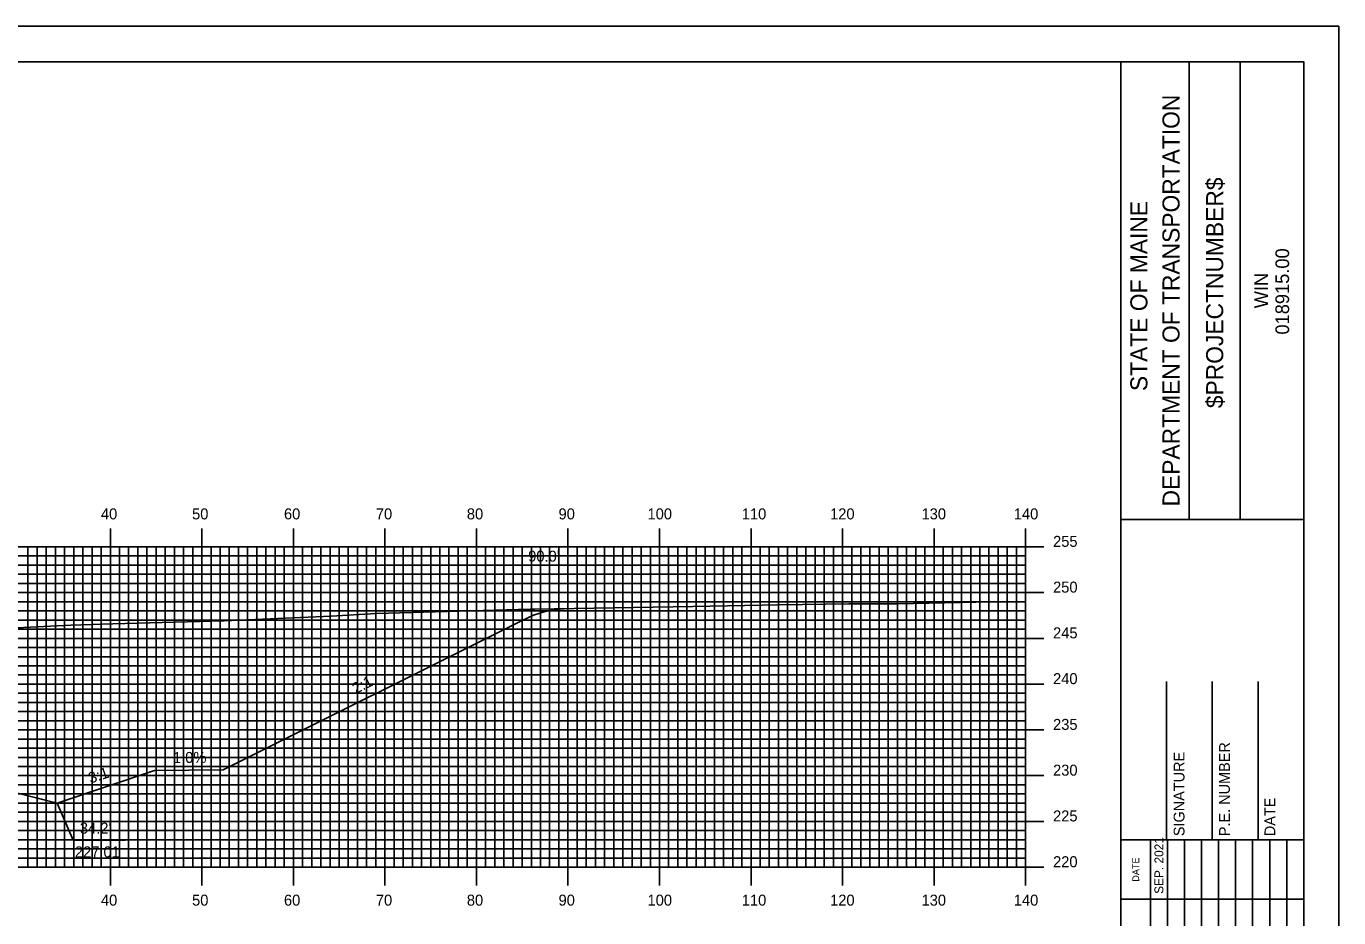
# Model space of a CAD drawing. Extents: x 1817670 to 1818013, y 442591 to 442811.
# Drawn here: x 1817866.4 to 1818009.8, y 442713.1 to 442810.5 of the extents above; entities that cross this region are included whole.
import ezdxf

# ---------------------------------------------------------------- set-up
doc = ezdxf.new("R2010")
doc.units = 0
for name, color, linetype in [('ANNOTATION', 7, 'Continuous'), ('BORDER', 7, 'Continuous'), ('D_Roadway_Centerline', 7, 'Continuous'), ('D_Roadway_SlopeLines', 7, 'Continuous'), ('D_Text_Standard', 7, 'Continuous'), ('H_V ANNOTATION', 7, 'Continuous'), ('MAJOR', 7, 'Continuous'), ('MINOR', 7, 'Continuous'), ('PLOT BOUNDARY', 7, 'Continuous'), ('S_Roadway_Centerline', 7, 'Continuous')]:
    doc.layers.add(name, color=color, linetype=linetype)

msp = doc.modelspace()

# ---------------------------------------------------------------- linework, layer by layer
at = {"layer": 'ANNOTATION'}
msp.add_lwpolyline([(1817877.24, 442721.62), (1817871.55, 442721.62), (1817869.79, 442725.67)], dxfattribs=at)
at = {"layer": 'BORDER'}
for p, q in [((1817986.01, 442596.67), (1817986.01, 442806.67)), ((1817993.47, 442756.66), (1817993.47, 442806.66)), ((1817999.06, 442756.66), (1817999.06, 442806.66)), ((1817986.01, 442756.65), (1818006.01, 442756.65)), ((1817991.01, 442721.67), (1817991.01, 442738.97)), ((1817996.01, 442721.67), (1817996.01, 442738.97)), ((1818001.01, 442721.67), (1818001.01, 442738.97)), ((1817986.01, 442721.67), (1818006.01, 442721.67))]:
    msp.add_line(p, q, dxfattribs=at)
msp.add_lwpolyline([(1817686.01, 442596.67), (1818006.01, 442596.67), (1818006.01, 442806.67), (1817686.01, 442806.67)], close=True, dxfattribs=at)
for points in [[(1817989.24, 442715.17), (1817989.24, 442721.67)], [(1817991.11, 442686.68), (1817991.11, 442721.67)], [(1817992.97, 442721.67), (1817992.97, 442686.68)], [(1817994.83, 442686.68), (1817994.83, 442721.67)], [(1817996.7, 442686.68), (1817996.7, 442721.67)], [(1817998.56, 442686.68), (1817998.56, 442721.67)], [(1818000.42, 442686.68), (1818000.42, 442721.67)], [(1818002.29, 442686.68), (1818002.29, 442721.67)], [(1818004.15, 442686.68), (1818004.15, 442721.67)], [(1817989.24, 442686.68), (1817989.24, 442720.26)], [(1817986.01, 442715.17), (1818006.01, 442715.17)]]:
    msp.add_lwpolyline(points, dxfattribs=at)
at = {"layer": 'D_Roadway_Centerline'}
msp.add_lwpolyline([(1817745.61, 442736.37), (1817746.86, 442736.45), (1817748.11, 442736.32), (1817749.36, 442736), (1817750.61, 442735.48), (1817762.56, 442729.5), (1817790.81, 442729.22), (1817801.44, 442725.67), (1817805.44, 442726.67), (1817815.61, 442729.22), (1817823.61, 442729.54), (1817835.61, 442729.78), (1817847.61, 442729.54), (1817855.61, 442729.22), (1817865.79, 442726.67), (1817869.79, 442725.67), (1817880.42, 442729.22), (1817887.92, 442729.29), (1817920.61, 442745.64), (1817921.86, 442746.19), (1817923.11, 442746.59), (1817924.36, 442746.83), (1817925.61, 442746.93)], dxfattribs=at)
at = {"layer": 'D_Roadway_SlopeLines'}
for points in [[(1817880.42, 442729.22), (1817887.92, 442729.29), (1817920.61, 442745.64), (1817921.86, 442746.19), (1817923.11, 442746.59), (1817924.36, 442746.83), (1817925.61, 442746.93)], [(1817855.61, 442729.22), (1817869.79, 442725.67)], [(1817869.79, 442725.67), (1817880.42, 442729.22)]]:
    msp.add_lwpolyline(points, dxfattribs=at)
at = {"layer": 'MAJOR'}
for p, q in [((1817875.61, 442755.67), (1817875.61, 442753.67)), ((1817885.61, 442755.67), (1817885.61, 442753.67)), ((1817895.61, 442755.67), (1817895.61, 442753.67)), ((1817905.61, 442755.67), (1817905.61, 442753.67)), ((1817915.61, 442755.67), (1817915.61, 442753.67)), ((1817925.61, 442755.67), (1817925.61, 442753.67)), ((1817935.61, 442755.67), (1817935.61, 442753.67)), ((1817945.61, 442755.67), (1817945.61, 442753.67)), ((1817955.61, 442755.67), (1817955.61, 442753.67)), ((1817965.61, 442755.67), (1817965.61, 442753.67)), ((1817975.61, 442755.67), (1817975.61, 442753.67)), ((1817695.61, 442753.67), (1817975.61, 442753.67)), ((1817695.61, 442753.67), (1817975.61, 442753.67)), ((1817875.61, 442718.67), (1817875.61, 442753.67)), ((1817885.61, 442718.67), (1817885.61, 442753.67)), ((1817895.61, 442718.67), (1817895.61, 442753.67)), ((1817905.61, 442718.67), (1817905.61, 442753.67)), ((1817915.61, 442718.67), (1817915.61, 442753.67)), ((1817925.61, 442718.67), (1817925.61, 442753.67)), ((1817935.61, 442718.67), (1817935.61, 442753.67)), ((1817945.61, 442718.67), (1817945.61, 442753.67)), ((1817955.61, 442718.67), (1817955.61, 442753.67)), ((1817965.61, 442718.67), (1817965.61, 442753.67)), ((1817977.62, 442753.67), (1817973.61, 442753.67)), ((1817975.61, 442718.67), (1817975.61, 442753.67)), ((1817975.61, 442718.67), (1817975.61, 442753.67)), ((1817695.61, 442748.67), (1817975.61, 442748.67)), ((1817977.62, 442748.67), (1817973.61, 442748.67)), ((1817695.61, 442743.67), (1817975.61, 442743.67)), ((1817977.62, 442743.67), (1817973.61, 442743.67)), ((1817695.61, 442738.67), (1817975.61, 442738.67)), ((1817977.62, 442738.67), (1817973.61, 442738.67)), ((1817695.61, 442733.67), (1817975.61, 442733.67)), ((1817977.62, 442733.67), (1817973.61, 442733.67)), ((1817695.61, 442728.67), (1817975.61, 442728.67)), ((1817977.62, 442728.67), (1817973.61, 442728.67)), ((1817695.61, 442723.67), (1817975.61, 442723.67)), ((1817977.62, 442723.67), (1817973.61, 442723.67)), ((1817695.61, 442718.67), (1817975.61, 442718.67)), ((1817695.61, 442718.67), (1817975.61, 442718.67)), ((1817875.61, 442716.66), (1817875.61, 442718.67)), ((1817885.61, 442716.66), (1817885.61, 442718.67)), ((1817895.61, 442716.66), (1817895.61, 442718.67)), ((1817905.61, 442716.66), (1817905.61, 442718.67)), ((1817915.61, 442716.66), (1817915.61, 442718.67)), ((1817925.61, 442716.66), (1817925.61, 442718.67)), ((1817935.61, 442716.66), (1817935.61, 442718.67)), ((1817945.61, 442716.66), (1817945.61, 442718.67)), ((1817955.61, 442716.66), (1817955.61, 442718.67)), ((1817965.61, 442716.66), (1817965.61, 442718.67)), ((1817977.62, 442718.67), (1817973.61, 442718.67)), ((1817975.61, 442716.66), (1817975.61, 442718.67))]:
    msp.add_line(p, q, dxfattribs=at)
at = {"layer": 'MINOR'}
for p, q in [((1817695.61, 442752.67), (1817975.61, 442752.67)), ((1817866.61, 442718.67), (1817866.61, 442753.67)), ((1817867.61, 442718.67), (1817867.61, 442753.67)), ((1817868.61, 442718.67), (1817868.61, 442753.67)), ((1817869.61, 442718.67), (1817869.61, 442753.67)), ((1817870.61, 442718.67), (1817870.61, 442753.67)), ((1817871.61, 442718.67), (1817871.61, 442753.67)), ((1817872.61, 442718.67), (1817872.61, 442753.67)), ((1817873.61, 442718.67), (1817873.61, 442753.67)), ((1817874.61, 442718.67), (1817874.61, 442753.67)), ((1817876.61, 442718.67), (1817876.61, 442753.67)), ((1817877.61, 442718.67), (1817877.61, 442753.67)), ((1817878.61, 442718.67), (1817878.61, 442753.67)), ((1817879.61, 442718.67), (1817879.61, 442753.67)), ((1817880.61, 442718.67), (1817880.61, 442753.67)), ((1817881.61, 442718.67), (1817881.61, 442753.67)), ((1817882.61, 442718.67), (1817882.61, 442753.67)), ((1817883.61, 442718.67), (1817883.61, 442753.67)), ((1817884.61, 442718.67), (1817884.61, 442753.67)), ((1817886.61, 442718.67), (1817886.61, 442753.67)), ((1817887.61, 442718.67), (1817887.61, 442753.67)), ((1817888.61, 442718.67), (1817888.61, 442753.67)), ((1817889.61, 442718.67), (1817889.61, 442753.67)), ((1817890.61, 442718.67), (1817890.61, 442753.67)), ((1817891.61, 442718.67), (1817891.61, 442753.67)), ((1817892.61, 442718.67), (1817892.61, 442753.67)), ((1817893.61, 442718.67), (1817893.61, 442753.67)), ((1817894.61, 442718.67), (1817894.61, 442753.67)), ((1817896.61, 442718.67), (1817896.61, 442753.67)), ((1817897.61, 442718.67), (1817897.61, 442753.67)), ((1817898.61, 442718.67), (1817898.61, 442753.67)), ((1817899.61, 442718.67), (1817899.61, 442753.67)), ((1817900.61, 442718.67), (1817900.61, 442753.67)), ((1817901.61, 442718.67), (1817901.61, 442753.67)), ((1817902.61, 442718.67), (1817902.61, 442753.67)), ((1817903.61, 442718.67), (1817903.61, 442753.67)), ((1817904.61, 442718.67), (1817904.61, 442753.67)), ((1817906.61, 442718.67), (1817906.61, 442753.67)), ((1817907.61, 442718.67), (1817907.61, 442753.67)), ((1817908.61, 442718.67), (1817908.61, 442753.67)), ((1817909.61, 442718.67), (1817909.61, 442753.67)), ((1817910.61, 442718.67), (1817910.61, 442753.67)), ((1817911.61, 442718.67), (1817911.61, 442753.67)), ((1817912.61, 442718.67), (1817912.61, 442753.67)), ((1817913.61, 442718.67), (1817913.61, 442753.67)), ((1817914.61, 442718.67), (1817914.61, 442753.67)), ((1817916.61, 442718.67), (1817916.61, 442753.67)), ((1817917.61, 442718.67), (1817917.61, 442753.67)), ((1817918.61, 442718.67), (1817918.61, 442753.67)), ((1817919.61, 442718.67), (1817919.61, 442753.67)), ((1817920.61, 442718.67), (1817920.61, 442753.67)), ((1817921.61, 442718.67), (1817921.61, 442753.67)), ((1817922.61, 442718.67), (1817922.61, 442753.67)), ((1817923.61, 442718.67), (1817923.61, 442753.67)), ((1817924.61, 442718.67), (1817924.61, 442753.67)), ((1817926.61, 442718.67), (1817926.61, 442753.67)), ((1817927.61, 442718.67), (1817927.61, 442753.67)), ((1817928.61, 442718.67), (1817928.61, 442753.67)), ((1817929.61, 442718.67), (1817929.61, 442753.67)), ((1817930.61, 442718.67), (1817930.61, 442753.67)), ((1817931.61, 442718.67), (1817931.61, 442753.67)), ((1817932.61, 442718.67), (1817932.61, 442753.67)), ((1817933.61, 442718.67), (1817933.61, 442753.67)), ((1817934.61, 442718.67), (1817934.61, 442753.67)), ((1817936.61, 442718.67), (1817936.61, 442753.67)), ((1817937.61, 442718.67), (1817937.61, 442753.67)), ((1817938.61, 442718.67), (1817938.61, 442753.67)), ((1817939.61, 442718.67), (1817939.61, 442753.67)), ((1817940.61, 442718.67), (1817940.61, 442753.67)), ((1817941.61, 442718.67), (1817941.61, 442753.67)), ((1817942.61, 442718.67), (1817942.61, 442753.67)), ((1817943.61, 442718.67), (1817943.61, 442753.67)), ((1817944.61, 442718.67), (1817944.61, 442753.67)), ((1817946.61, 442718.67), (1817946.61, 442753.67)), ((1817947.61, 442718.67), (1817947.61, 442753.67)), ((1817948.61, 442718.67), (1817948.61, 442753.67)), ((1817949.61, 442718.67), (1817949.61, 442753.67)), ((1817950.61, 442718.67), (1817950.61, 442753.67)), ((1817951.61, 442718.67), (1817951.61, 442753.67)), ((1817952.61, 442718.67), (1817952.61, 442753.67)), ((1817953.61, 442718.67), (1817953.61, 442753.67)), ((1817954.61, 442718.67), (1817954.61, 442753.67)), ((1817956.61, 442718.67), (1817956.61, 442753.67)), ((1817957.61, 442718.67), (1817957.61, 442753.67)), ((1817958.61, 442718.67), (1817958.61, 442753.67)), ((1817959.61, 442718.67), (1817959.61, 442753.67)), ((1817960.61, 442718.67), (1817960.61, 442753.67)), ((1817961.61, 442718.67), (1817961.61, 442753.67)), ((1817962.61, 442718.67), (1817962.61, 442753.67)), ((1817963.61, 442718.67), (1817963.61, 442753.67)), ((1817964.61, 442718.67), (1817964.61, 442753.67)), ((1817966.61, 442718.67), (1817966.61, 442753.67)), ((1817967.61, 442718.67), (1817967.61, 442753.67)), ((1817968.61, 442718.67), (1817968.61, 442753.67)), ((1817969.61, 442718.67), (1817969.61, 442753.67)), ((1817970.61, 442718.67), (1817970.61, 442753.67)), ((1817971.61, 442718.67), (1817971.61, 442753.67)), ((1817972.61, 442718.67), (1817972.61, 442753.67)), ((1817973.61, 442718.67), (1817973.61, 442753.67)), ((1817975.61, 442752.67), (1817973.61, 442752.67)), ((1817974.61, 442718.67), (1817974.61, 442753.67)), ((1817695.61, 442751.67), (1817975.61, 442751.67)), ((1817975.61, 442751.67), (1817973.61, 442751.67)), ((1817695.61, 442750.67), (1817975.61, 442750.67)), ((1817975.61, 442750.67), (1817973.61, 442750.67)), ((1817695.61, 442749.67), (1817975.61, 442749.67)), ((1817975.61, 442749.67), (1817973.61, 442749.67)), ((1817695.61, 442747.67), (1817975.61, 442747.67)), ((1817975.61, 442747.67), (1817973.61, 442747.67)), ((1817695.61, 442746.67), (1817975.61, 442746.67)), ((1817695.61, 442745.67), (1817975.61, 442745.67)), ((1817975.61, 442746.67), (1817973.61, 442746.67)), ((1817975.61, 442745.67), (1817973.61, 442745.67)), ((1817695.61, 442744.67), (1817975.61, 442744.67)), ((1817975.61, 442744.67), (1817973.61, 442744.67)), ((1817695.61, 442742.67), (1817975.61, 442742.67)), ((1817975.61, 442742.67), (1817973.61, 442742.67)), ((1817695.61, 442741.67), (1817975.61, 442741.67)), ((1817975.61, 442741.67), (1817973.61, 442741.67)), ((1817695.61, 442740.67), (1817975.61, 442740.67)), ((1817975.61, 442740.67), (1817973.61, 442740.67)), ((1817695.61, 442739.67), (1817975.61, 442739.67)), ((1817975.61, 442739.67), (1817973.61, 442739.67)), ((1817695.61, 442737.67), (1817975.61, 442737.67)), ((1817975.61, 442737.67), (1817973.61, 442737.67)), ((1817695.61, 442736.67), (1817975.61, 442736.67)), ((1817695.61, 442735.67), (1817975.61, 442735.67)), ((1817975.61, 442736.67), (1817973.61, 442736.67)), ((1817975.61, 442735.67), (1817973.61, 442735.67)), ((1817695.61, 442734.67), (1817975.61, 442734.67)), ((1817975.61, 442734.67), (1817973.61, 442734.67)), ((1817695.61, 442732.67), (1817975.61, 442732.67)), ((1817975.61, 442732.67), (1817973.61, 442732.67)), ((1817695.61, 442731.67), (1817975.61, 442731.67)), ((1817975.61, 442731.67), (1817973.61, 442731.67)), ((1817695.61, 442730.67), (1817975.61, 442730.67)), ((1817975.61, 442730.67), (1817973.61, 442730.67)), ((1817695.61, 442729.67), (1817975.61, 442729.67)), ((1817975.61, 442729.67), (1817973.61, 442729.67)), ((1817695.61, 442727.67), (1817975.61, 442727.67)), ((1817975.61, 442727.67), (1817973.61, 442727.67)), ((1817695.61, 442726.67), (1817975.61, 442726.67)), ((1817695.61, 442725.67), (1817975.61, 442725.67)), ((1817975.61, 442726.67), (1817973.61, 442726.67)), ((1817975.61, 442725.67), (1817973.61, 442725.67)), ((1817695.61, 442724.67), (1817975.61, 442724.67)), ((1817975.61, 442724.67), (1817973.61, 442724.67)), ((1817695.61, 442722.67), (1817975.61, 442722.67)), ((1817975.61, 442722.67), (1817973.61, 442722.67)), ((1817695.61, 442721.67), (1817975.61, 442721.67)), ((1817975.61, 442721.67), (1817973.61, 442721.67)), ((1817695.61, 442720.67), (1817975.61, 442720.67)), ((1817695.61, 442719.67), (1817975.61, 442719.67)), ((1817975.61, 442720.67), (1817973.61, 442720.67)), ((1817975.61, 442719.67), (1817973.61, 442719.67))]:
    msp.add_line(p, q, dxfattribs=at)
at = {"layer": 'PLOT BOUNDARY'}
msp.add_lwpolyline([(1817669.83, 442590.55), (1818009.83, 442590.55), (1818009.83, 442810.55), (1817669.83, 442810.55)], close=True, dxfattribs=at)
at = {"layer": 'S_Roadway_Centerline'}
msp.add_lwpolyline([(1817855.7, 442744.33), (1817871.29, 442745.12), (1817875.89, 442745.27), (1817888.04, 442745.57), (1817899.73, 442746.1), (1817904.64, 442746.4), (1817921.49, 442746.86), (1817921.78, 442746.87), (1817921.84, 442746.87), (1817921.94, 442746.87), (1817939.26, 442747.14), (1817948.67, 442747.33), (1817956.3, 442747.44), (1817961.66, 442747.44), (1817973.61, 442747.68), (1817975.61, 442747.62)], dxfattribs=at)

# ---------------------------------------------------------------- texts
at = {"layer": 'ANNOTATION'}
for s, rotation, p in [('2:1', 26.5651, (1817902.41, 442737.57)), ('1.0%', 0.5729, (1817882.46, 442730.04)), ('3:1', 18.4349, (1817873.44, 442727.8))]:
    msp.add_text(s, height=1.2, rotation=rotation, dxfattribs=at).set_placement(p)
for s, p in [("34.2'", (1817872.28, 442722.34)), ('227.01', (1817871.74, 442719.74))]:
    msp.add_text(s, height=1.2, dxfattribs=at).set_placement(p)
at = {"layer": 'BORDER'}
for s, height, p in [('DEPARTMENT OF TRANSPORTATION', 1.8635, (1817992.43, 442758.08)), ('$PROJECTNUMBER$', 1.8635, (1817997.2, 442768.82)), ('STATE OF MAINE', 1.8635, (1817988.92, 442770.69)), ('018915.00', 1.491, (1818004.4, 442776.86)), ('WIN', 1.491, (1818002.09, 442779.73)), ('SIGNATURE', 1.181, (1817992.97, 442722.06)), ('P.E. NUMBER', 1.1811, (1817997.93, 442722.06)), ('DATE', 1.181, (1818002.89, 442722.06)), ('SEP. 2021', 0.969, (1817990.66, 442715.76)), ('DATE', 0.743, (1817988.02, 442717.08))]:
    msp.add_text(s, height=height, rotation=90, dxfattribs=at).set_placement(p)
at = {"layer": 'D_Text_Standard'}
msp.add_text("90.0'", height=1.2, dxfattribs=at).set_placement((1817921.26, 442752.05))
at = {"layer": 'H_V ANNOTATION'}
for s, p in [('40', (1817874.58, 442756.67)), ('50', (1817884.54, 442756.67)), ('60', (1817894.58, 442756.67)), ('70', (1817904.62, 442756.67)), ('80', (1817914.56, 442756.67)), ('90', (1817924.58, 442756.67)), ('100', (1817934.3, 442756.67)), ('110', (1817944.6, 442756.67)), ('120', (1817954.25, 442756.67)), ('130', (1817964.24, 442756.67)), ('140', (1817974.32, 442756.67)), ('255', (1817978.61, 442753.67)), ('250', (1817978.61, 442748.67)), ('245', (1817978.61, 442743.67)), ('240', (1817978.61, 442738.67)), ('235', (1817978.61, 442733.67)), ('230', (1817978.61, 442728.67)), ('225', (1817978.61, 442723.67)), ('220', (1817978.61, 442718.67)), ('40', (1817874.58, 442714.47)), ('50', (1817884.54, 442714.47)), ('60', (1817894.58, 442714.47)), ('70', (1817904.62, 442714.47)), ('80', (1817914.56, 442714.47)), ('90', (1817924.58, 442714.47)), ('100', (1817934.3, 442714.47)), ('110', (1817944.6, 442714.47)), ('120', (1817954.25, 442714.47)), ('130', (1817964.24, 442714.47)), ('140', (1817974.32, 442714.47))]:
    msp.add_text(s, height=1.2, dxfattribs=at).set_placement(p)

doc.saveas('drawing.dxf')
